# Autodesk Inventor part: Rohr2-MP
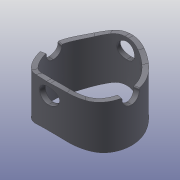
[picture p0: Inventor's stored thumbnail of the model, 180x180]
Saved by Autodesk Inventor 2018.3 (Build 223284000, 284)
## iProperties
Created: 2020-01
Part Number: Rohr2-MP
Material: 1.0570 S355J2
Document SubType Name: Modeling
Designer: M.S.
Mass: 6779.7 g
Surface Area: 1591.99 cm^2
Volume: 863.656 cm^3
Density: 7.85 g/cm^3
Appearance: Metall - Stahl
Author: M.S.
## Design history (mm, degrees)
sketch "Skizze1"
  geometry: C1 r 109.55 at (0, 0); C2 r 97.05 at (0, 0); 1 further point
  constraints: 2 centre point, 1 coincident
  dimensions: "d0" = 219.1 diameter of C1; "d1" = 12.5 radial gap between concentric circles of C1 C2
extrude "Extrusion1" new body sketch "Skizze1" distance "d2" = 145; taper "d3" = 0 deg
sketch "Skizze2" dims "d5" = 20.5, "d6" = 23.5 (computed from d5)
  geometry: L1 (-97.05, 0)-(97.05, 0) reference; 3 further points; 1 other entity
  constraints: 1 midpoint, 1 vertical alignment, 2 other
  dimensions: "d4" = 30.5 distance from line of point (0, -30.5) L1
extrude "Bohrungen1" cut sketch "Skizze2" extent not by distance; stored distance "d7" = 145; taper "d8" = 0 deg
sketch "Skizze3" dims "d9" = 20.5, "d11" = 20 (computed from d9)
  geometry: L1 (-97.05, 0)-(97.05, 0) reference; L2 (-20, -30.5)-(-20, 0); L3 (20, -30.5)-(20, 0); L4 (-20, 0)-(20, 0); 3 further points; 1 other entity
  constraints: 6 end point, 2 point on line, 2 vertical, 1 horizontal alignment, 1 midpoint, 1 perpendicular, 1 vertical alignment, 4 other
  dimensions: "d10" = 30.5 distance of point (0, -30.5) point (0, 0) (= d4)
extrude "Bohrungen2" cut sketch "Skizze3" extent not by distance; stored distance "d12" = 145; taper "d13" = 0 deg
sketch "Skizze4"
  geometry: L1 (-107.709, -30.5)-(-94.967, -30.5) reference; L2 (94.967, -30.5)-(107.709, -30.5) reference; L3 (-94.967, 0)-(94.967, 0) reference; L4 (-94.967, 0)-(-94.967, -30.5) reference; L5 (-107.709, -30.5)-(-107.709, 0) reference; L6 (-107.709, 0)-(-94.967, 0) reference; L7 (-71.061, -18.543)-(-41.648, -6.957); L8 (-107.709, -25.5)-(-107.709, 0); L9 (-107.709, 0)-(-5, 0); A1 r 100 centre (-5, -100) between (-5, 0) and (-41.648, -6.957); A2 r 100 centre (-107.709, 74.5) between (-107.709, -25.5) and (-71.061, -18.543); 1 further point
  constraints: 6 end point, 4 point on circle, 3 tangent, 2 centre point, 2 point on line, 1 equal radius, 1 line through centre, 1 perpendicular, 1 vertical
  dimensions: "d16" = 5 distance from line of L8.start L1; "d17" = 5 distance of point (0, 0) L9.end; "d18" = 100 radius of A1
extrude "Extrusion4" cut sketch "Skizze4" extent not by distance; stored distance "d19" = 145; taper "d20" = 0 deg
mirror "Spiegeln1"
sketch "Skizze5"
  geometry: L1 (-109.55, -145)-(109.55, -145) reference; L2 (-109.55, -51)-(-109.55, -145) reference; L3 (109.55, -51)-(109.55, -145) reference; L4 (0, -191.986)-(0, 128.623) reference; L5 (-75.086, -137.196)-(-34.464, -117.804); L6 (75.086, -137.196)-(34.464, -117.804); L7 (-109.55, -145)-(109.55, -145); A1 r 80 centre (-109.55, -65) between (-109.55, -145) and (-75.086, -137.196); A2 r 80 centre (0, -190) between (0, -110) and (-34.464, -117.804); A3 r 80 centre (109.55, -65) between (75.086, -137.196) and (109.55, -145); A4 r 80 centre (0, -190) between (34.464, -117.804) and (0, -110); 2 further points
  constraints: 8 point on circle, 6 end point, 5 symmetric about line, 4 centre point, 3 tangent, 1 collinear, 1 equal radius, 1 line through centre, 1 point on line, 2 other
  dimensions: "d21" = 110 distance of A2.start point (0, 0); "d23" = 80 radius of A2
extrude "Extrusion5" cut sketch "Skizze5" extent not by distance; stored distance "d24" = 145; taper "d25" = 0 deg
fillet "Rundung1" dims "d26" = 4
feature "Verdickung1" dims "d29" = 12.5, "d30" = 12.5
feature "Verdickung2" dims "d31" = 12.5, "d32" = 12.5
node "Volumenkörper1"
